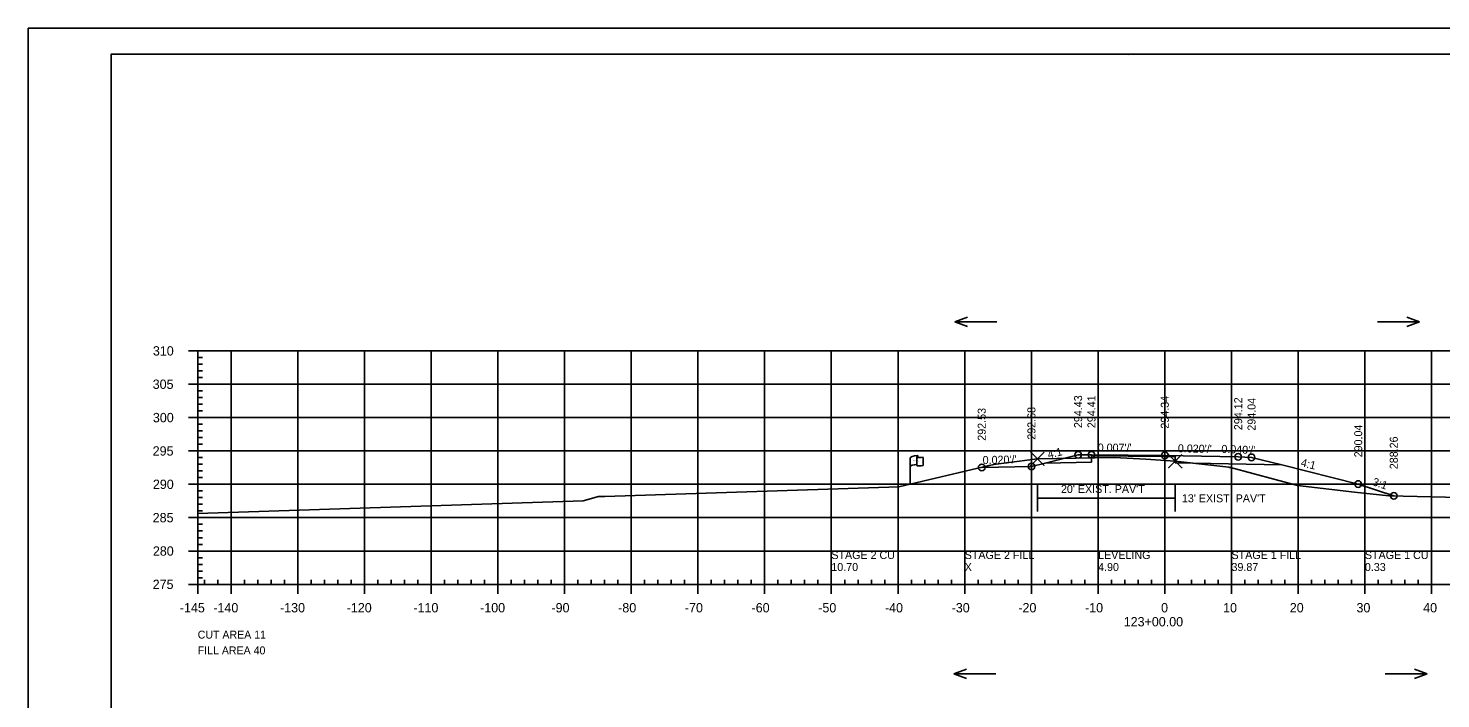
# Model space of a CAD drawing. Extents: x 1370843 to 1371177, y 380307 to 382654.
# Drawn here: x 1370843.3 to 1371055.1, y 382127 to 382227.5 of the extents above; entities that cross this region are included whole.
import ezdxf

# ---------------------------------------------------------------- set-up
doc = ezdxf.new("R2010")
doc.units = 0
for name, color, linetype in [('R_Alt Surface', 7, 'Continuous'), ('R_Axis', 7, 'Continuous'), ('R_Axis Annot', 7, 'Continuous'), ('R_Border', 7, 'Continuous'), ('R_Border Notes', 7, 'Continuous'), ('R_Exist Surface', 7, 'Continuous'), ('R_Exist Surface Annot', 7, 'Continuous'), ('R_Fin Surface', 7, 'Continuous'), ('R_Fin Surface Annot', 7, 'Continuous'), ('R_Grid', 7, 'Continuous'), ('R_No Plot', 7, 'Continuous'), ('R_ROW', 7, 'Continuous'), ('R_Water Annot', 7, 'Continuous')]:
    doc.layers.add(name, color=color, linetype=linetype)

msp = doc.modelspace()

# ---------------------------------------------------------------- linework, layer by layer
at = {"layer": 'R_Alt Surface'}
msp.add_lwpolyline([(1370995.77, 382162.34), (1371002.71, 382162.48), (1371002.71, 382163.4), (1371013.71, 382163.32), (1371015.27, 382163.29), (1371015.27, 382162.38), (1371031.25, 382162.06)], dxfattribs=at)
at = {"layer": 'R_Axis'}
for p, q in [((1370867.31, 382179.15), (1370868.71, 382179.15)), ((1370868.71, 382144.15), (1370868.71, 382179.15)), ((1370868.71, 382178.15), (1370869.41, 382178.15)), ((1370868.71, 382177.15), (1370869.41, 382177.15)), ((1370868.71, 382176.15), (1370869.41, 382176.15)), ((1370868.71, 382175.15), (1370869.41, 382175.15)), ((1370867.31, 382174.15), (1370868.71, 382174.15)), ((1370868.71, 382173.15), (1370869.41, 382173.15)), ((1370868.71, 382172.15), (1370869.41, 382172.15)), ((1370868.71, 382171.15), (1370869.41, 382171.15)), ((1370867.31, 382169.15), (1370868.71, 382169.15)), ((1370868.71, 382170.15), (1370869.41, 382170.15)), ((1370868.71, 382168.15), (1370869.41, 382168.15)), ((1370868.71, 382167.15), (1370869.41, 382167.15)), ((1370868.71, 382166.15), (1370869.41, 382166.15)), ((1370867.31, 382164.15), (1370868.71, 382164.15)), ((1370868.71, 382165.15), (1370869.41, 382165.15)), ((1370868.71, 382163.15), (1370869.41, 382163.15)), ((1370868.71, 382162.15), (1370869.41, 382162.15)), ((1370868.71, 382161.15), (1370869.41, 382161.15)), ((1370868.71, 382160.15), (1370869.41, 382160.15)), ((1370867.31, 382159.15), (1370868.71, 382159.15)), ((1370868.71, 382158.15), (1370869.41, 382158.15)), ((1370868.71, 382157.15), (1370869.41, 382157.15)), ((1370868.71, 382156.15), (1370869.41, 382156.15)), ((1370867.31, 382154.15), (1370868.71, 382154.15)), ((1370868.71, 382155.15), (1370869.41, 382155.15)), ((1370868.71, 382153.15), (1370869.41, 382153.15)), ((1370868.71, 382152.15), (1370869.41, 382152.15)), ((1370868.71, 382151.15), (1370869.41, 382151.15)), ((1370867.31, 382149.15), (1370868.71, 382149.15)), ((1370868.71, 382150.15), (1370869.41, 382150.15)), ((1370868.71, 382148.15), (1370869.41, 382148.15)), ((1370868.71, 382147.15), (1370869.41, 382147.15)), ((1370868.71, 382146.15), (1370869.41, 382146.15)), ((1370868.71, 382145.15), (1370869.41, 382145.15)), ((1370868.71, 382144.15), (1370868.71, 382144.85)), ((1370869.71, 382144.15), (1370869.71, 382144.85)), ((1370871.71, 382144.15), (1370871.71, 382144.85)), ((1370875.71, 382144.15), (1370875.71, 382144.85)), ((1370877.71, 382144.15), (1370877.71, 382144.85)), ((1370879.71, 382144.15), (1370879.71, 382144.85)), ((1370881.71, 382144.15), (1370881.71, 382144.85)), ((1370885.71, 382144.15), (1370885.71, 382144.85)), ((1370887.71, 382144.15), (1370887.71, 382144.85)), ((1370889.71, 382144.15), (1370889.71, 382144.85)), ((1370891.71, 382144.15), (1370891.71, 382144.85)), ((1370895.71, 382144.15), (1370895.71, 382144.85)), ((1370897.71, 382144.15), (1370897.71, 382144.85)), ((1370899.71, 382144.15), (1370899.71, 382144.85)), ((1370901.71, 382144.15), (1370901.71, 382144.85)), ((1370905.71, 382144.15), (1370905.71, 382144.85)), ((1370907.71, 382144.15), (1370907.71, 382144.85)), ((1370909.71, 382144.15), (1370909.71, 382144.85)), ((1370911.71, 382144.15), (1370911.71, 382144.85)), ((1370915.71, 382144.15), (1370915.71, 382144.85)), ((1370917.71, 382144.15), (1370917.71, 382144.85)), ((1370919.71, 382144.15), (1370919.71, 382144.85)), ((1370921.71, 382144.15), (1370921.71, 382144.85)), ((1370925.71, 382144.15), (1370925.71, 382144.85)), ((1370927.71, 382144.15), (1370927.71, 382144.85)), ((1370929.71, 382144.15), (1370929.71, 382144.85)), ((1370931.71, 382144.15), (1370931.71, 382144.85)), ((1370935.71, 382144.15), (1370935.71, 382144.85)), ((1370937.71, 382144.15), (1370937.71, 382144.85)), ((1370939.71, 382144.15), (1370939.71, 382144.85)), ((1370941.71, 382144.15), (1370941.71, 382144.85)), ((1370945.71, 382144.15), (1370945.71, 382144.85)), ((1370947.71, 382144.15), (1370947.71, 382144.85)), ((1370949.71, 382144.15), (1370949.71, 382144.85)), ((1370951.71, 382144.15), (1370951.71, 382144.85)), ((1370955.71, 382144.15), (1370955.71, 382144.85)), ((1370957.71, 382144.15), (1370957.71, 382144.85)), ((1370959.71, 382144.15), (1370959.71, 382144.85)), ((1370961.71, 382144.15), (1370961.71, 382144.85)), ((1370965.71, 382144.15), (1370965.71, 382144.85)), ((1370967.71, 382144.15), (1370967.71, 382144.85)), ((1370969.71, 382144.15), (1370969.71, 382144.85)), ((1370971.71, 382144.15), (1370971.71, 382144.85)), ((1370975.71, 382144.15), (1370975.71, 382144.85)), ((1370977.71, 382144.15), (1370977.71, 382144.85)), ((1370979.71, 382144.15), (1370979.71, 382144.85)), ((1370981.71, 382144.15), (1370981.71, 382144.85)), ((1370985.71, 382144.15), (1370985.71, 382144.85)), ((1370987.71, 382144.15), (1370987.71, 382144.85)), ((1370989.71, 382144.15), (1370989.71, 382144.85)), ((1370991.71, 382144.15), (1370991.71, 382144.85)), ((1370995.71, 382144.15), (1370995.71, 382144.85)), ((1370997.71, 382144.15), (1370997.71, 382144.85)), ((1370999.71, 382144.15), (1370999.71, 382144.85)), ((1371001.71, 382144.15), (1371001.71, 382144.85)), ((1371005.71, 382144.15), (1371005.71, 382144.85)), ((1371007.71, 382144.15), (1371007.71, 382144.85)), ((1371009.71, 382144.15), (1371009.71, 382144.85)), ((1371011.71, 382144.15), (1371011.71, 382144.85)), ((1371015.71, 382144.15), (1371015.71, 382144.85)), ((1371017.71, 382144.15), (1371017.71, 382144.85)), ((1371019.71, 382144.15), (1371019.71, 382144.85)), ((1371021.71, 382144.15), (1371021.71, 382144.85)), ((1371025.71, 382144.15), (1371025.71, 382144.85)), ((1371027.71, 382144.15), (1371027.71, 382144.85)), ((1371029.71, 382144.15), (1371029.71, 382144.85)), ((1371031.71, 382144.15), (1371031.71, 382144.85)), ((1371035.71, 382144.15), (1371035.71, 382144.85)), ((1371037.71, 382144.15), (1371037.71, 382144.85)), ((1371039.71, 382144.15), (1371039.71, 382144.85)), ((1371041.71, 382144.15), (1371041.71, 382144.85)), ((1371045.71, 382144.15), (1371045.71, 382144.85)), ((1371047.71, 382144.15), (1371047.71, 382144.85)), ((1371049.71, 382144.15), (1371049.71, 382144.85)), ((1371051.71, 382144.15), (1371051.71, 382144.85)), ((1370867.31, 382144.15), (1370868.71, 382144.15)), ((1370868.71, 382144.15), (1371158.71, 382144.15)), ((1370868.71, 382142.75), (1370868.71, 382144.15)), ((1370873.71, 382142.75), (1370873.71, 382144.15)), ((1370883.71, 382142.75), (1370883.71, 382144.15)), ((1370893.71, 382142.75), (1370893.71, 382144.15)), ((1370903.71, 382142.75), (1370903.71, 382144.15)), ((1370913.71, 382142.75), (1370913.71, 382144.15)), ((1370923.71, 382142.75), (1370923.71, 382144.15)), ((1370933.71, 382142.75), (1370933.71, 382144.15)), ((1370943.71, 382142.75), (1370943.71, 382144.15)), ((1370953.71, 382142.75), (1370953.71, 382144.15)), ((1370963.71, 382142.75), (1370963.71, 382144.15)), ((1370973.71, 382142.75), (1370973.71, 382144.15)), ((1370983.71, 382142.75), (1370983.71, 382144.15)), ((1370993.71, 382142.75), (1370993.71, 382144.15)), ((1371003.71, 382142.75), (1371003.71, 382144.15)), ((1371013.71, 382142.75), (1371013.71, 382144.15)), ((1371023.71, 382142.75), (1371023.71, 382144.15)), ((1371033.71, 382142.75), (1371033.71, 382144.15)), ((1371043.71, 382142.75), (1371043.71, 382144.15)), ((1371053.71, 382142.75), (1371053.71, 382144.15))]:
    msp.add_line(p, q, dxfattribs=at)
at = {"layer": 'R_Border'}
for p, q in [((1370855.71, 382223.61), (1371171.89, 382223.61)), ((1370855.71, 382018.15), (1370855.71, 382223.61)), ((1371008.23, 382223.35), (1371008.23, 382223.35)), ((1371008.23, 382223.35), (1371008.23, 382223.35))]:
    msp.add_line(p, q, dxfattribs=at)
at = {"layer": 'R_Exist Surface'}
msp.add_line((1370926.52, 382156.69), (1370868.71, 382154.79), dxfattribs=at)
msp.add_lwpolyline([(1370926.52, 382156.69), (1370928.81, 382157.3), (1370929.27, 382157.31), (1370929.74, 382157.33), (1370973.85, 382158.79), (1370987.4, 382161.95), (1370988.12, 382162.12), (1370988.44, 382162.16), (1370994.6, 382162.98), (1371000.43, 382163.09), (1371006.14, 382163.16), (1371010.87, 382162.9), (1371015.27, 382162.63), (1371023.3, 382161.7), (1371023.43, 382161.69), (1371023.58, 382161.65), (1371033.58, 382158.96), (1371042.16, 382157.97), (1371047.32, 382157.43), (1371074.92, 382156.75), (1371083.23, 382156.46)], dxfattribs=at)
at = {"layer": 'R_Exist Surface Annot'}
for p, q in [((1370994.6, 382155.05), (1370994.6, 382159.05)), ((1371015.27, 382155.05), (1371015.27, 382159.05)), ((1370994.6, 382157.05), (1371015.27, 382157.05))]:
    msp.add_line(p, q, dxfattribs=at)
at = {"layer": 'R_Fin Surface'}
msp.add_lwpolyline([(1370986.26, 382161.68), (1370993.7, 382161.83), (1370993.71, 382161.83), (1370995.77, 382162.34), (1371000.71, 382163.58), (1371002.71, 382163.57), (1371013.71, 382163.49), (1371024.71, 382163.27), (1371026.71, 382163.19), (1371031.25, 382162.06), (1371042.71, 382159.19), (1371048.04, 382157.41)], dxfattribs=at)
at = {"layer": 'R_Grid'}
for p, q in [((1370868.71, 382179.15), (1371158.71, 382179.15)), ((1370868.71, 382144.15), (1370868.71, 382179.15)), ((1370873.71, 382144.15), (1370873.71, 382179.15)), ((1370883.71, 382144.15), (1370883.71, 382179.15)), ((1370893.71, 382144.15), (1370893.71, 382179.15)), ((1370903.71, 382144.15), (1370903.71, 382179.15)), ((1370913.71, 382144.15), (1370913.71, 382179.15)), ((1370923.71, 382144.15), (1370923.71, 382179.15)), ((1370933.71, 382144.15), (1370933.71, 382179.15)), ((1370943.71, 382144.15), (1370943.71, 382179.15)), ((1370953.71, 382144.15), (1370953.71, 382179.15)), ((1370963.71, 382144.15), (1370963.71, 382179.15)), ((1370973.71, 382144.15), (1370973.71, 382179.15)), ((1370983.71, 382144.15), (1370983.71, 382179.15)), ((1370993.71, 382144.15), (1370993.71, 382179.15)), ((1371003.71, 382144.15), (1371003.71, 382179.15)), ((1371013.71, 382144.15), (1371013.71, 382179.15)), ((1371023.71, 382144.15), (1371023.71, 382179.15)), ((1371033.71, 382144.15), (1371033.71, 382179.15)), ((1371043.71, 382144.15), (1371043.71, 382179.15)), ((1371053.71, 382144.15), (1371053.71, 382179.15)), ((1370868.71, 382174.15), (1371158.71, 382174.15)), ((1370868.71, 382169.15), (1371158.71, 382169.15)), ((1370868.71, 382164.15), (1371158.71, 382164.15)), ((1370868.71, 382159.15), (1371158.71, 382159.15)), ((1370868.71, 382154.15), (1371158.71, 382154.15)), ((1370868.71, 382149.15), (1371158.71, 382149.15)), ((1370868.71, 382144.15), (1371158.71, 382144.15))]:
    msp.add_line(p, q, dxfattribs=at)
at = {"layer": 'R_No Plot'}
msp.add_line((1370843.31, 382227.51), (1371176.64, 382227.51), dxfattribs=at)
for points in [[(1370843.3, 382227.51), (1371176.64, 382227.51), (1371176.64, 382014.17), (1370843.3, 382014.17)], [(1371089.63, 382223.61), (1371089.63, 382213.73), (1371125.36, 382213.73), (1371125.36, 382210.81), (1371148.56, 382210.81), (1371148.56, 382186.48), (1371171.89, 382186.48), (1371171.89, 382018.15), (1370855.71, 382018.15), (1370855.71, 382223.61)], [(1370986.26, 382161.68), (1370987.4, 382161.95), (1370988.12, 382162.12), (1370988.44, 382162.16), (1370994.6, 382162.98), (1371000.43, 382163.09), (1371002.71, 382163.11), (1371002.71, 382162.48), (1370995.77, 382162.34), (1370993.71, 382161.83)], [(1371002.71, 382163.11), (1371006.14, 382163.16), (1371010.87, 382162.9), (1371015.27, 382162.63), (1371015.27, 382163.29), (1371013.71, 382163.32), (1371002.71, 382163.4)], [(1371015.27, 382162.63), (1371017.9, 382162.32), (1371015.27, 382162.38)], [(1371017.9, 382162.32), (1371023.3, 382161.7), (1371023.43, 382161.69), (1371023.58, 382161.65), (1371033.58, 382158.96), (1371042.16, 382157.97), (1371047.32, 382157.43), (1371048.04, 382157.41), (1371042.71, 382159.19), (1371031.25, 382162.06)]]:
    msp.add_lwpolyline(points, close=True, dxfattribs=at)
for points in [[(1370994.6, 382162.98), (1370993.6, 382163.98), (1370994.6, 382162.98), (1370993.6, 382161.98), (1370994.6, 382162.98), (1370995.6, 382161.98), (1370994.6, 382162.98), (1370995.6, 382163.98)], [(1371015.27, 382162.63), (1371014.27, 382163.63), (1371015.27, 382162.63), (1371014.27, 382161.63), (1371015.27, 382162.63), (1371016.27, 382161.63), (1371015.27, 382162.63), (1371016.27, 382163.63)]]:
    msp.add_lwpolyline(points, dxfattribs=at)
for centre in [(1371000.71, 382163.58), (1371002.71, 382163.57), (1371013.71, 382163.49), (1370986.26, 382161.68), (1370993.71, 382161.83), (1371024.71, 382163.27), (1371026.71, 382163.19), (1371042.71, 382159.19), (1371048.04, 382157.41)]:
    msp.add_circle(centre, 0.5, dxfattribs=at)
at = {"layer": 'R_ROW'}
for p, q in [((1370975.54, 382159.19), (1370975.54, 382163.14)), ((1370976.54, 382163.23), (1370976.54, 382163.22)), ((1370976.54, 382163.22), (1370976.54, 382161.99)), ((1370976.7, 382163.39), (1370976.7, 382163.15)), ((1370977.47, 382163.19), (1370977.47, 382161.95))]:
    msp.add_line(p, q, dxfattribs=at)
for centre, radius, start, end in [((1370976.61, 382163.23), 0.078, 88.6458, 274.2828), ((1370976.61, 382161.99), 0.0783, 180, 273.9564), ((1370976.62, 382163.39), 0.0783, 263.0712, 93.9564)]:
    msp.add_arc(centre, radius, start, end, dxfattribs=at)
for centre, major_axis, ratio, start_param, end_param in [((1370977.12, 382163.18), (-1.58, -0.04), 0.19887, 5.030368, 6.283185), ((1370977.12, 382161.86), (-1.58, -0.04), 0.19887, 5.083035, 6.194897), ((1370977.83, 382163.3), (-1.23, -0.13), 0.052933, 0.159456, 1.268315), ((1370977.83, 382162.06), (-1.23, -0.13), 0.052933, 0.159456, 1.268315)]:
    msp.add_ellipse(centre, major_axis=major_axis, ratio=ratio, start_param=start_param, end_param=end_param, dxfattribs=at)
at = {"layer": 'R_Water Annot'}
for p, q in [((1370982.23, 382183.48), (1370984.15, 382184.18)), ((1370988.51, 382183.48), (1370982.23, 382183.48)), ((1370982.23, 382183.48), (1370984.15, 382182.78)), ((1371045.62, 382183.48), (1371051.9, 382183.48)), ((1371051.9, 382183.48), (1371049.98, 382184.18)), ((1371051.9, 382183.48), (1371049.98, 382182.78)), ((1370982.07, 382130.74), (1370983.99, 382131.44)), ((1370988.36, 382130.74), (1370982.07, 382130.74)), ((1370982.07, 382130.74), (1370983.99, 382130.04)), ((1371046.77, 382130.74), (1371053.05, 382130.74)), ((1371053.05, 382130.74), (1371051.13, 382131.44)), ((1371053.05, 382130.74), (1371051.13, 382130.04))]:
    msp.add_line(p, q, dxfattribs=at)

# ---------------------------------------------------------------- texts
at = {"layer": 'R_Axis Annot'}
for s, p in [('310', (1370861.99, 382178.45)), ('305', (1370861.96, 382173.45)), ('300', (1370861.99, 382168.45)), ('295', (1370861.96, 382163.45)), ('290', (1370861.99, 382158.45)), ('285', (1370861.96, 382153.45)), ('280', (1370861.99, 382148.45)), ('275', (1370861.96, 382143.45)), ('-145', (1370866.03, 382139.95)), ('-140', (1370871.05, 382139.95)), ('-130', (1370881.05, 382139.95)), ('-120', (1370891.05, 382139.95)), ('-110', (1370901.05, 382139.95)), ('-100', (1370911.05, 382139.95)), ('-90', (1370921.75, 382139.95)), ('-80', (1370931.75, 382139.95)), ('-70', (1370941.75, 382139.95)), ('-60', (1370951.75, 382139.95)), ('-50', (1370961.75, 382139.95)), ('-40', (1370971.75, 382139.95)), ('-30', (1370981.75, 382139.95)), ('-20', (1370991.75, 382139.95)), ('-10', (1371001.75, 382139.95)), ('0', (1371013.15, 382139.95)), ('10', (1371022.45, 382139.95)), ('20', (1371032.45, 382139.95)), ('30', (1371042.45, 382139.95)), ('40', (1371052.45, 382139.95)), ('123+00.00', (1371007.55, 382137.85))]:
    msp.add_text(s, height=1.4, dxfattribs=at).set_placement(p)
at = {"layer": 'R_Border Notes'}
for s, p in [('CUT AREA 11', (1370868.71, 382136.02)), ('FILL AREA 40', (1370868.71, 382133.66))]:
    msp.add_text(s, height=1.1875, dxfattribs=at).set_placement(p)
at = {"layer": 'R_Exist Surface Annot'}
msp.add_text("20' EXIST. PAV'T", height=1.2, dxfattribs=at).set_placement((1370998.14, 382157.85))
at = {"layer": 'R_Fin Surface Annot'}
for s, rotation, p in [('294.43', 90, (1371001.31, 382167.58)), ('294.41', 90, (1371003.31, 382167.57)), ('294.34', 90, (1371014.31, 382167.49)), ('292.53', 90, (1370986.86, 382165.68)), ('292.68', 90, (1370994.31, 382165.83)), ('294.12', 90, (1371025.31, 382167.27)), ('294.04', 90, (1371027.31, 382167.19)), ('290.04', 90, (1371043.31, 382163.19)), ('288.26', 90, (1371048.64, 382161.41)), ('4:1', 14.0362, (1370996.28, 382162.99)), ("0.007'/'", 359.6097, (1371003.65, 382164.06)), ("0.020'/'", 358.8542, (1371015.66, 382163.95)), ("0.040'/'", 357.7094, (1371022.17, 382163.87)), ("0.020'/'", 1.1458, (1370986.41, 382162.18)), ('4:1', 345.9638, (1371034.02, 382161.88)), ('3:1', 341.5651, (1371044.74, 382159.04))]:
    msp.add_text(s, height=1.2, rotation=rotation, dxfattribs=at).set_placement(p)
at = {"layer": 'R_No Plot'}
for s, p in [("13' EXIST. PAV'T", (1371016.27, 382156.45)), ('STAGE 2 CUT', (1370963.71, 382147.95)), ('STAGE 2 FILL', (1370983.71, 382147.95)), ('LEVELING', (1371003.71, 382147.95)), ('STAGE 1 FILL', (1371023.71, 382147.95)), ('STAGE 1 CUT', (1371043.71, 382147.95)), ('10.70', (1370963.71, 382146.15)), ('X', (1370983.71, 382146.15)), ('4.90', (1371003.71, 382146.15)), ('39.87', (1371023.71, 382146.15)), ('0.33', (1371043.71, 382146.15))]:
    msp.add_text(s, height=1.2, dxfattribs=at).set_placement(p)
at = {"layer": 'R_ROW'}
for s, height, rotation, p in [('R ', 0.2, 9.9884, (1370976.06, 382162.64)), (' O', 0.2, 9.9884, (1370976.21, 382162.68)), ('W', 0.2, 351.1788, (1370976.54, 382162.51)), ('DWB 11-9-07', 0.001, 90, (1370976.7, 382163.15)), ('DWB 11-9-07', 0.001, 5.0717, (1370977.46, 382161.95)), ('DWB 11-9-07', 0.001, 90, (1370975.54, 382159.19))]:
    msp.add_text(s, height=height, rotation=rotation, dxfattribs=at).set_placement(p)

doc.saveas('drawing.dxf')
